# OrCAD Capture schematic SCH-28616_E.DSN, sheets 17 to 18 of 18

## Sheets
17 M-03 USB OTG / HOST: size C
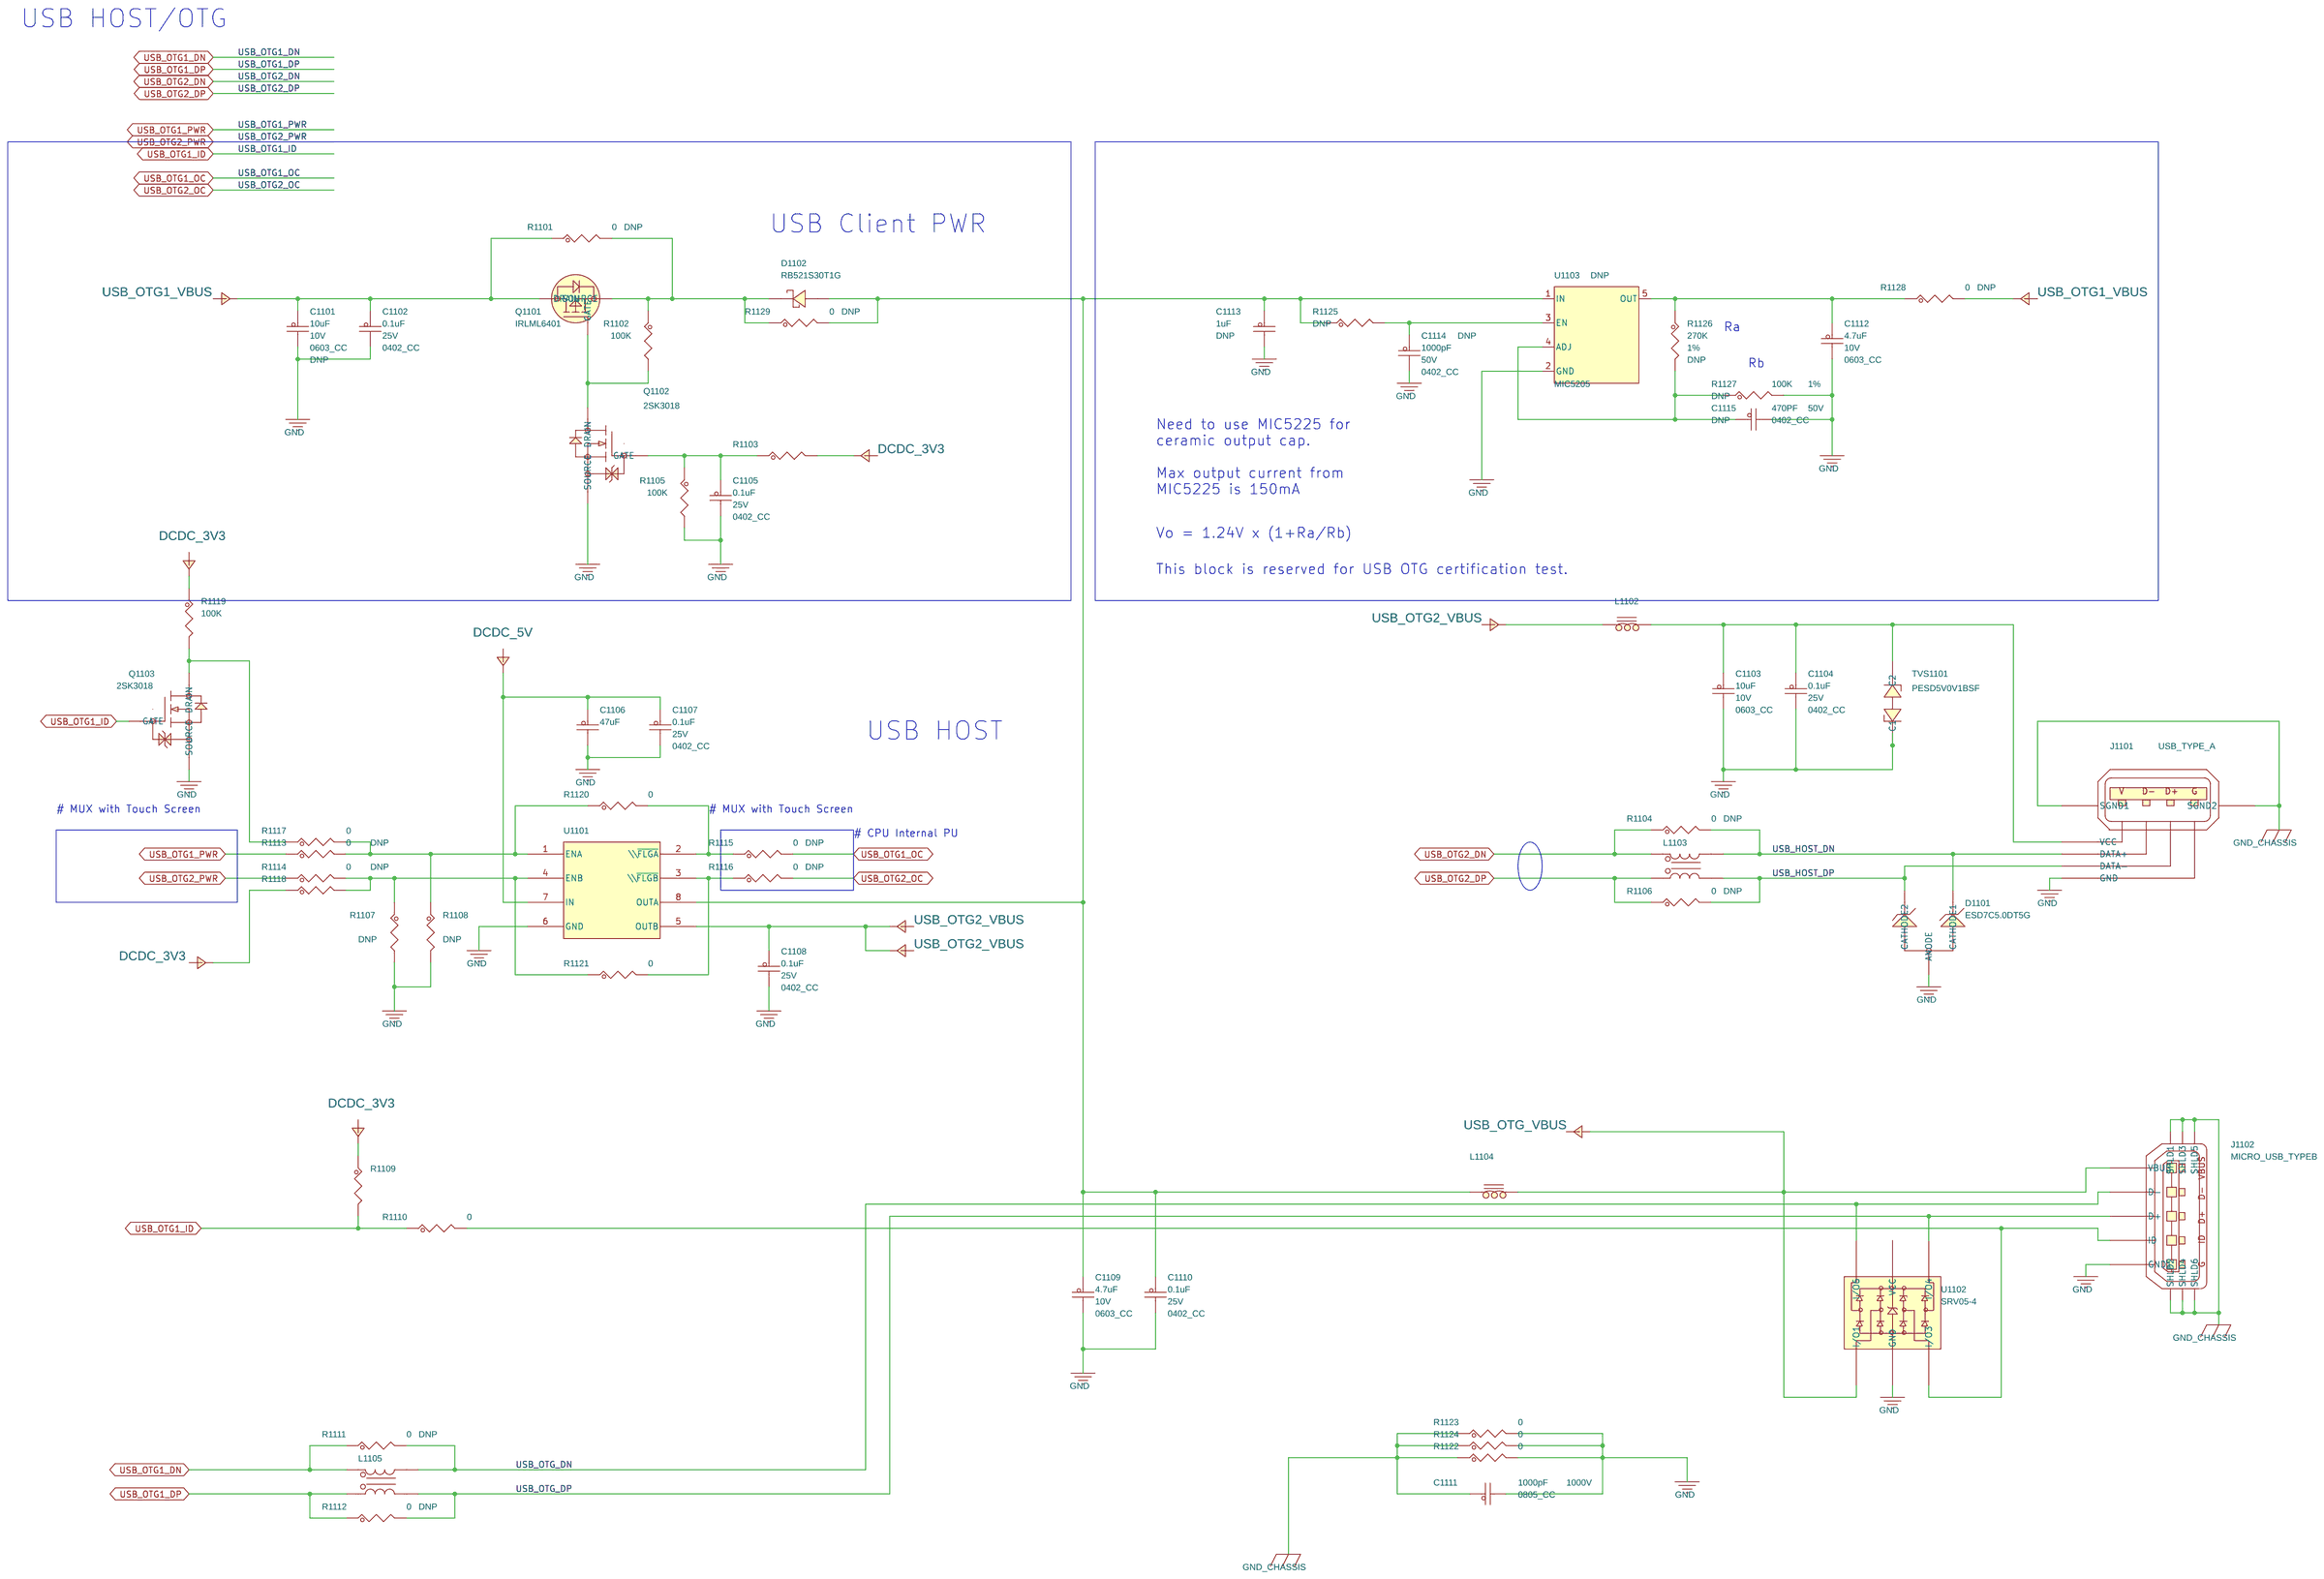
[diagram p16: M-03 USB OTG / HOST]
18 M-09 SD/BT/ARDUINO: size C
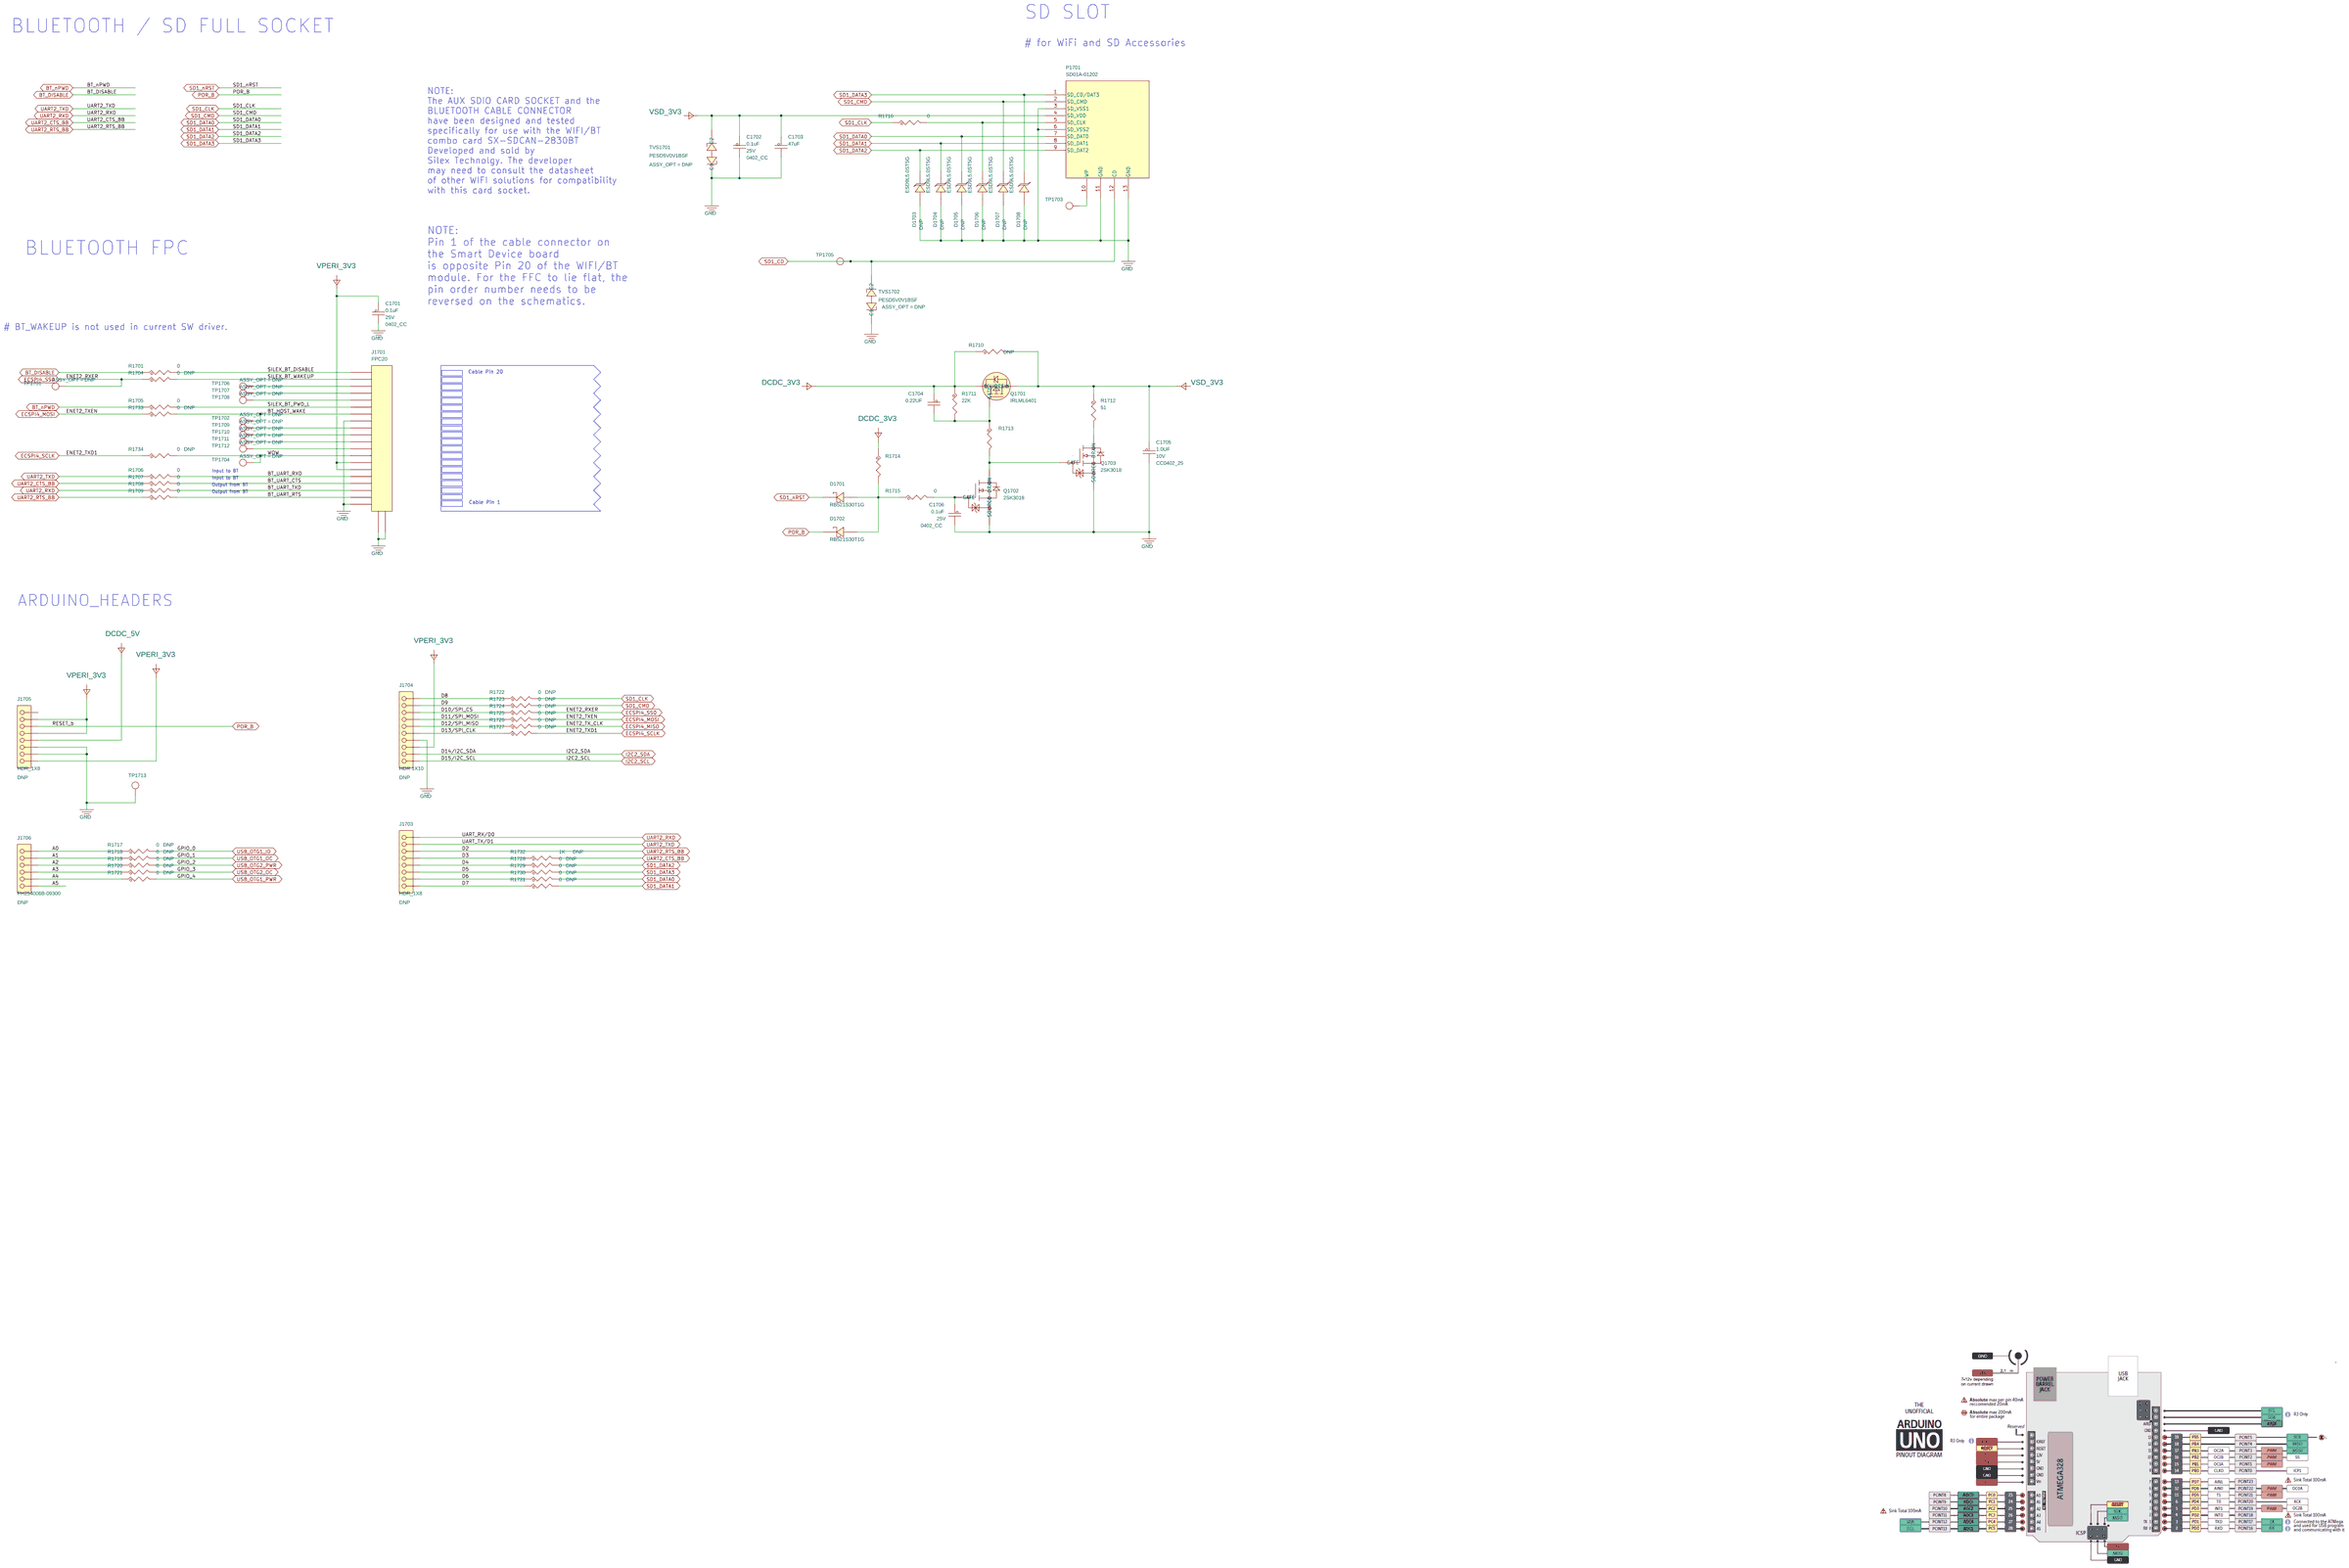
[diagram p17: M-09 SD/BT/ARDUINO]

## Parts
sheet M-03 USB OTG / HOST
C1101  10uF  [0603_CC]
C1102  0.1uF  [0402_CC]
C1103  10uF  [0603_CC]
C1104  0.1uF  [0402_CC]
C1105  0.1uF  [0402_CC]
C1106  47uF  [0805_CC]
C1107  0.1uF  [0402_CC]
C1108  0.1uF  [0402_CC]
C1109  4.7uF  [0603_CC]
C1110  0.1uF  [0402_CC]
C1111  1000pF  [0805_CC]
C1112  4.7uF  [0603_CC]
C1113  1uF  [0402_CC]
C1114  1000pF  [0402_CC]
C1115  470PF  [0402_CC]
D1101  ESD7C5.0DT5G  [sot-723]
D1102  RB521S30T1G  [sod_523]
J1101  USB_TYPE_A  [con4_usb_a_fe_ra_th]
J1102  MICRO_USB_TYPEB  [con_usb_type_b_sm]
L1102  120OHM  [0603_CC]
L1103  90OHM  [ind4_choke_0805]
L1104  120OHM  [0603_CC]
L1105  90OHM  [ind4_choke_0805]
Q1101  IRLML6401  [sot-23]
Q1102  2SK3018  [SOT323_3]
Q1103  2SK3018  [SOT323_3]
R1101  0  [0402_CC]
R1102  100K  [0402_CC]
R1103  10K  [0402_CC]
R1104  0  [0402_CC]
R1105  100K  [0402_CC]
R1106  0  [0402_CC]
R1107  10K  [0402_CC]
R1108  10K  [0402_CC]
R1109  10K  [0402_CC]
R1110  0  [0402_CC]
R1111  0  [0402_CC]
R1112  0  [0402_CC]
R1113  0  [0402_CC]
R1114  0  [0402_CC]
R1115  0  [0402_CC]
R1116  0  [0402_CC]
R1117  0  [0402_CC]
R1118  10K  [0402_CC]
R1119  100K  [0402_CC]
R1120  0  [0402_CC]
R1121  0  [0402_CC]
R1122  0  [0805_CC]
R1123  0  [0805_CC]
R1124  0  [0805_CC]
R1125  10K  [0402_CC]
R1126  270K  [RC0402_25]
R1127  100K  [RC0402_25]
R1128  0  [0402_CC]
R1129  0  [0402_CC]
TVS1101  PESD5V0V1BSF  [dsn0603-2]
U1101  MIC2026-1YM  [SO8]
U1102  SRV05-4  [SOT23_S6]
U1103  MIC5205  [sot23-20x60-5]
sheet M-09 SD/BT/ARDUINO
C1701  0.1uF  [0402_CC]
C1702  0.1uF  [0402_CC]
C1703  47uF  [0805_CC]
C1704  0.22UF  [CC0402_25]
C1705  1.0UF  [CC0402_25]
C1706  0.1uF  [0402_CC]
D1701  RB521S30T1G  [sod_523]
D1702  RB521S30T1G  [sod_523]
D1703  ESD9L5.0ST5G  [sod-923]
D1704  ESD9L5.0ST5G  [sod-923]
D1705  ESD9L5.0ST5G  [sod-923]
D1706  ESD9L5.0ST5G  [sod-923]
D1707  ESD9L5.0ST5G  [sod-923]
D1708  ESD9L5.0ST5G  [sod-923]
J1701  FPC20  [con_fpc_20_0p5_ra_f050_2sh]
J1703  HDR_1X8  [JUMP1X8-6040]
J1704  HDR 1X10  [hdr110]
J1705  HDR_1X8  [JUMP1X8-6040]
J1706  PH254006B-09300  [hdr106_b]
P1701  SD01A-01202  [con9_sdcard_28x29mm_smt]
Q1701  IRLML6401  [sot-23]
Q1702  2SK3018  [SOT323_3]
Q1703  2SK3018  [SOT323_3]
R1701  0  [0402_CC]
R1704  0  [0402_CC]
R1705  0  [0402_CC]
R1706  0  [0402_CC]
R1707  0  [0402_CC]
R1708  0  [0402_CC]
R1709  0  [0402_CC]
R1710  0  [0603_CC]
R1711  22K  [0402_CC]
R1712  51  [0402_CC]
R1713  10K  [0402_CC]
R1714  10K  [0402_CC]
R1715  0  [0402_CC]
R1716  0  [0402_CC]
R1717  0  [0402_CC]
R1718  0  [0402_CC]
R1719  0  [0402_CC]
R1720  0  [0402_CC]
R1721  0  [0402_CC]
R1722  0  [0402_CC]
R1723  0  [0402_CC]
R1724  0  [0402_CC]
R1725  0  [0402_CC]
R1726  0  [0402_CC]
R1727  0  [0402_CC]
R1728  0  [0402_CC]
R1729  0  [0402_CC]
R1730  0  [0402_CC]
R1731  0  [0402_CC]
R1732  1K  [0402_CC]
R1733  0  [0402_CC]
R1734  0  [0402_CC]
TP1701  TPAD_020  [tpad_020]
TP1702  TPAD_020  [tpad_020]
TP1703  TPAD_020  [tpad_020]
TP1704  TPAD_020  [tpad_020]
TP1705  TPAD_020  [tpad_020]
TP1706  TPAD_020  [tpad_020]
TP1707  TPAD_020  [tpad_020]
TP1708  TPAD_020  [tpad_020]
TP1709  TPAD_020  [tpad_020]
TP1710  TPAD_020  [tpad_020]
TP1711  TPAD_020  [tpad_020]
TP1712  TPAD_020  [tpad_020]
TP1713  TEST POINT WHITE  [TEST_LOOP]
TVS1701  PESD5V0V1BSF  [dsn0603-2]
TVS1702  PESD5V0V1BSF  [dsn0603-2]

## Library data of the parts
C1101 = CAP_NP: CAP CER 10UF 10V 20% X5R 0603; AGILE_PN: 150-78609; ASSY_OPT: DNP; CAD_APPROVED: Yes; FPLIST: CC0603_OV,CC0603,0603_CC; HEIGHT: 1.016MM; MFG_NAME01: TAIYO YUDEN; MFG_PN01: LMK107BJ106MALTD; Package Size: 0603; Package Type: Paper Tape; ROHS: Yes; Rated Voltage: 10V; Temp Range: -55C to +85C; Tolerance: 20%; VOLTAGE: 10V
C1102 C1104 C1105 C1107 C1108 C1110 C1701 C1702 C1706 = CAP_NP: CAP CER 0.1UF 25V 10% X5R 0402; AGILE_PN: 150-78633; CAD_APPROVED: Yes; FPLIST: CC0402_25,CC0402_HD,0402_CC; HEIGHT: 0.55MM; MFG_NAME01: YAGEO AMERICA; MFG_PN01: CC0402KRX5R8BB104; Package Size: 0402; ROHS: Yes; Rated Voltage: 25V; Temp Range: -55C to +85C; Tolerance: 10%; VOLTAGE: 25V
C1103 = CAP_NP: CAP CER 10UF 10V 20% X5R 0603; AGILE_PN: 150-78609; CAD_APPROVED: Yes; FPLIST: CC0603_OV,CC0603,0603_CC; HEIGHT: 1.016MM; MFG_NAME01: TAIYO YUDEN; MFG_PN01: LMK107BJ106MALTD; Package Size: 0603; Package Type: Paper Tape; ROHS: Yes; Rated Voltage: 10V; Temp Range: -55C to +85C; Tolerance: 20%; VOLTAGE: 10V
C1106 C1703 = CAP_NP: CAP CER 47uF 10V 20% X5R 0805; AGILE_PN: 150-78979; CAD_APPROVED: Yes; FPLIST: CC0805_OV,CC0805,0805_CC; HEIGHT: 1.45 MM; MFG_NAME01: TDK; MFG_PN01: C2012X5R1A476M125AC; ROHS: Yes; Rated Voltage: 10V; Temp Range: -55C to +85C; Tolerance: 20%; VOLTAGE: 10V
C1109 C1112 = CAP_NP: CAP CER 4.7UF 10V 10% X5R 0603; AGILE_PN: 150-77975; CAD_APPROVED: Yes; FPLIST: CC0603_OV,CC0603,0603_CC; HEIGHT: 0.9MM; MFG_NAME01: FENGHUA; MFG_PN01: 0603X475K100NT; Package Size: 0603; Package Type: tape & reel; ROHS: Yes; Rated Voltage: 10V; Temp Range: -55C to +85C; Tolerance: 10%; VOLTAGE: 10V
C1111 = CAP_NP: CAP CER 1000pF 1000V 10% X7R 0805; AGILE_PN: 150-78841; CAD_APPROVED: Yes; FPLIST: CC0805_OV,CC0805,0805_CC; HEIGHT: 1.4MM; MFG_NAME01: KEMET; MFG_PN01: C0805C102KDRACTU; Package Size: 0805; Package Type: Tape & reel; ROHS: Yes; Rated Voltage: 1000V; Temp Range: -55C to +125C; Tolerance: 10%; VOLTAGE: 1000V
C1113 = CAP_NP: CAP CER 1uF 16V 10% X5R 0402; AGILE_PN: 150-78973; ASSY_OPT: DNP; CAD_APPROVED: Yes; FPLIST: CC0402_25,CC0402_HD,0402_CC; HEIGHT: 0.55 MM; MFG_NAME01: YAGEO; MFG_PN01: CC0402KRX5R7BB105; ROHS: Yes; Rated Voltage: 16V; Temp Range: -55C to +85C; Tolerance: 10%; VOLTAGE: 16V
C1114 = CAP_NP: CAP CER 1000PF 50V X7R 5% 0402; AGILE_PN: 150-75774; ASSY_OPT: DNP; CAD_APPROVED: Yes; FPLIST: CC0402_25,CC0402_HD,0402_CC; HEIGHT: 0.6MM; MFG_NAME01: CAPAX TECHNOLOGIES INC.; MFG_PN01: 0402X102J500SNT; Package Size: 0402; Package Type: Tape&reel; ROHS: Yes; Rated Voltage: 50V; Temp Range: -55C to +125C; Tolerance: 5%; VOLTAGE: 50V
C1115 = CAP_NP: CAP CER 470PF 50V 10% X7R 0402; AGILE_PN: 150-75452; ASSY_OPT: DNP; CAD_APPROVED: Yes; FPLIST: CC0402_25,CC0402_HD,0402_CC; HEIGHT: 0.55MM; MFG_NAME01: WALSIN TECHNOLOGY CORP.; MFG_PN01: 0402B471K500CT; PRIORITY_PN: 021-00340; ROHS: Yes; ROOM: RGMII_PHY; Rated Voltage: 50V; SIGNAL_MODEL: DEFAULT_CAPACITOR_470pF_2_1; Temp Range: -55C to +125C; Tolerance: 10%; VOLTAGE: 50V
D1101 = DZ_DUAL_CK_C1C2A: DIODE TVS 1A 5.0V AEC-Q101 SOT-723; 3D_Mechanical_Footprint_File: http://fcl.am.freescale.net/ALLEGRO/step/sot-723.STEP; AGILE_PN: 480-78836; CAD_APPROVED: Yes; HEIGHT: 0.55MM; MFG_NAME01: ON SEMICONDUCTOR; ROHS: Yes; Rated Voltage: 5V
D1102 D1701 D1702 = DIODE_SCHTKY: DIODE SCH 200MA 30V AEC-Q101 SOD-523; 3D_Mechanical_Footprint_File: http://fcl.am.freescale.net/ALLEGRO/step/sod_523.STEP; AGILE_PN: 480-78501; CAD_APPROVED: Yes; HEIGHT: 0.7MM; MFG_NAME01: ON SEMICONDUCTOR; ROHS: Yes; Rated Voltage: 30V
J1101 = USB_A: CON 1X4 RA SHLD TH USB_TYPE_A_FEMALE -- 321H AU 118L; AGILE_PN: 210-80779; CAD_APPROVED: Yes; HEIGHT: 8.15MM; MFG_NAME01: SHENZHEN ATOM TECHNOLOGY CO.,LTD; MFG_PN01: USB304FA-A1005302; Package Type: TH; ROHS: Yes
J1102 = USB_MICRO_B_SKT: CON 1X5 MICROUSB_TYPE_B_FEMALE RA SHLD SMT 0.65MM SP 110H AU; AGILE_PN: 211-79712; CAD_APPROVED: Yes; HEIGHT: 2.795MM; MFG_NAME01: SHENZHEN ATOM TECHNOLOGY CO.,LTD; MFG_PN01: USB205FB-C1013203; ROHS: Yes
L1102 L1104 = BEAD_0: IND FER BEAD 120OHM@100MHZ 2A 25% 0603; AGILE_PN: 180-30008; CAD_APPROVED: Yes; FPLIST: IND_0603,0603_CC; HEIGHT: 0.95MM; MFG_NAME01: MURATA; MFG_PN01: BLM18PG121SH1; PART_TYPE: FERRITE; ROHS: Yes; Tolerance: 25%
L1103 L1105 = DLW43: IND CHK 90 OHM@100MHZ 330MA 25% 0805; 3D_Mechanical_Footprint_File: http://fcl.am.freescale.net/ALLEGRO/step/ind4_choke_0805_39h.STEP; AGILE_PN: 180-76336; CAD_APPROVED: Yes; HEIGHT: 1MM; MFG_NAME01: MURATA; MFG_PN01: DLW21HN900SQ2L; PART_TYPE: CHOKE; ROHS: Yes; Temp Range: -40°C to +85°C; Tolerance: 25%
Q1101 Q1701 = MOSFET_P: TRAN PMOS PWR 12V 4.3A SOT23; AGILE_PN: 480-77718; CAD_APPROVED: Yes; HEIGHT: 1.12MM; MFG_NAME01: INTERNATIONAL RECTIFIER; MFG_PN01: IRLML6401TRPBF; ROHS: Yes
Q1102 Q1103 Q1702 Q1703 = 2SK3018: TRANS MOSFET N-CH 30V .1A SOT-323; AGILE_PN: 480-75317; CAD_APPROVED: Yes; HEIGHT: 0.9MM; MFG_NAME01: ROHM; MFG_PN01: 2SK3018T106; ROHS: Yes
R1101 R1104 R1106 R1111-R1116 R1128 R1129 R1704 R1717-R1731 R1733 R1734 = RES: RES MF ZERO OHM 1/16W 5% 0402; AGILE_PN: 470-75394; ASSY_OPT: DNP; CAD_APPROVED: Yes; FPLIST: RC0402_25,RC0402_HD,RC0402_X2,0402_CC; HEIGHT: 0.45 MM; MFG_NAME01: YAGEO AMERICA; MFG_PN01: RC0402JR-070RL; ROHS: Yes; Tolerance: 5%
R1102 R1105 R1119 = RES: RES MF 100K 1/16W 5% 0402; AGILE_PN: 470-75597; CAD_APPROVED: Yes; FPLIST: RC0402_25,RC0402_HD,0402_CC; HEIGHT: 0.40 MM; MFG_NAME01: VENKEL COMPANY; MFG_PN01: CR0402-16W-104JT; ROHS: Yes; Temp Range: -55C to +155C; Temp_Range: -55C to +155C; Tolerance: 5%
R1103 R1109 R1118 = RES: RES MF 10K 1/16W 5% 0402; AGILE_PN: 470-75557; CAD_APPROVED: Yes; FPLIST: RC0402_25,RC0402_HD,0402_CC; HEIGHT: 0.4 MM; MFG_NAME01: VISHAY INTERTECHNOLOGY; MFG_PN01: CRCW040210K0JNED; ROHS: Yes; Tolerance: 5%
R1107 R1108 = RES: RES MF 10K 1/16W 5% 0402; AGILE_PN: 470-75557; ASSY_OPT: DNP; CAD_APPROVED: Yes; FPLIST: RC0402_25,RC0402_HD,0402_CC; HEIGHT: 0.4 MM; MFG_NAME01: VISHAY INTERTECHNOLOGY; MFG_PN01: CRCW040210K0JNED; ROHS: Yes; Tolerance: 5%
R1110 R1117 R1120 R1121 R1701 R1705-R1709 R1715 R1716 = RES: RES MF ZERO OHM 1/16W 5% 0402; AGILE_PN: 470-75394; CAD_APPROVED: Yes; FPLIST: RC0402_25,RC0402_HD,RC0402_X2,0402_CC; HEIGHT: 0.45 MM; MFG_NAME01: YAGEO AMERICA; MFG_PN01: RC0402JR-070RL; ROHS: Yes; Tolerance: 5%
R1122-R1124 = RES: RES MF ZERO OHM 1/8W -- 0805; AGILE_PN: 470-75442; CAD_APPROVED: Yes; FPLIST: RC0805_OV,RC0805,RC0805_OV_3P,0805_CC; HEIGHT: 0.7 MM; MFG_NAME01: YAGEO AMERICA; MFG_PN01: RC0805JR-070RL; ROHS: Yes; Temp Range: –55 °C to +155 °C; Tolerance: 5%
R1125 = RES: RES MF 10K 1/16W 5% 0402; AGILE_PN: 470-75557; ASSY_OPT: DNP; CAD_APPROVED: Yes; FPLIST: RC0402_25,RC0402_HD,0402_CC; HEIGHT: 0.4 MM; MFG_NAME01: VISHAY INTERTECHNOLOGY; MFG_PN01: CRCW040210K0JNED; ROHS: Yes; TOL: 5%; Tolerance: 5%
R1126 = RES: RES MF 270K 1/10W 1% AEC-Q200 0402; AGILE_PN: 470-31107; ASSY_OPT: DNP; CAD_APPROVED: Yes; FPLIST: RC0402_25,RC0402_HD,0402_CC; HEIGHT: 0.40 MM; MFG_NAME01: KOA SPEER; MFG_PN01: RK73H1ETTP2703F; ROHS: Yes; Temp Range: -55C to +155C; Temp_Range: -55C to +155C; Tolerance: 1%
R1127 = RES: RES MF 100K 1/16W 1% 0402; AGILE_PN: 470-76240; ASSY_OPT: DNP; CAD_APPROVED: Yes; FPLIST: RC0402_25,RC0402_HD,0402_CC; HEIGHT: 0.4MM; MFG_NAME01: VISHAY INTERTECHNOLOGY; MFG_PN01: CRCW0402100KFKEDC; ROHS: Yes; Tolerance: 1%
TVS1101 = DIODE_BIDIR: DIODE BIDIR ESD PROT 3.5pF 5V 1A SOD-962; 3D_Mechanical_Footprint_File: http://fcl.am.freescale.net/ALLEGRO/step/dsn0603-2.STEP; AGILE_PN: 480-79836; CAD_APPROVED: Yes; HEIGHT: 0.32MM; MFG_NAME01: NEXPERIA; MFG_PN01: PESD5V0V1BSF,315; Temp Range: -55°C to +150°C
U1101 = MIC2526_8P: IC LIN SW PWR ACTIVE HIGH DUAL 2.7V-5.5V 0.5A SOIC8; AGILE_PN: 312-75936; CAD_APPROVED: Yes; HEIGHT: 1.73mm; MFG_NAME01: MICREL; ROHS: Yes; VOLTAGE: 2.7-5.5V
U1102 = SRV05-4: DIODE TVS ARRAY 12A 5V 300W SOT23_S6; 3D_Mechanical_Footprint_File: http://fcl.am.freescale.net/ALLEGRO/step/SOT23_S6.STEP; AGILE_PN: 480-75205; CAD_APPROVED: Yes; HEIGHT: 1.45mm; MFG_NAME01: SEMTECH CORP; MFG_PN01: SRV05-4.TCT; ROHS: Yes; Rated Voltage: 5V
U1103 = MIC5205YM5_5P: IC LIN VREG LDO  1.5-15V 150MA 2.5-16V SOT23-5; 3D_Mechanical_Footprint_File: http://fcl.am.freescale.net/ALLEGRO/step/SOT23-20X60-5.STEP; AGILE_PN: 315-75304; ASSY_OPT: DNP; CAD_APPROVED: Yes; HEIGHT: 1.30MM; MFG_NAME01: MICREL; MFG_PN01: MIC5205YM5; ROHS: Yes; VOLTAGE: 2.5V to +16V
C1704 = CAP_NP: CAP CER 0.22UF 10V 10% X5R 0402; AGILE_PN: 150-77358; CAD_APPROVED: Yes; FPLIST: CC0402_25,CC0402_HD,0402_CC; HEIGHT: 0.55MM; MFG_NAME01: NIC COMPONENTS CORP; MFG_PN01: NMC0402X5R224K10TRPF; ROHS: Yes; Rated Voltage: 10V; Temp Range: -55C to +85C; Tolerance: 10%; VOLTAGE: 10V
C1705 = CAP_NP: CAP CER 1.0UF 10V 10% X5R 0402; AGILE_PN: 150-75772; CAD_APPROVED: Yes; FPLIST: CC0402_25,CC0402_HD,0402_CC; HEIGHT: 0.6MM; MFG_NAME01: YAGEO AMERICA; MFG_PN01: CC0402KRX5R6BB105; Package Size: 0402; ROHS: Yes; Rated Voltage: 10V; Temp Range: -55C to +85C; Tolerance: 10%; VOLTAGE: 10V
D1703-D1708 = DIODE_TVS: DIODE TVS ESD PROT ULT LOW CAP 5-5.4V SOD-923; 3D_Mechanical_Footprint_File: http://fcl.am.freescale.net/ALLEGRO/step/sod-923.STEP; AGILE_PN: 480-77934; ASSY_OPT: DNP; CAD_APPROVED: Yes; HEIGHT: 0.40MM; MFG_NAME01: ON SEMICONDUCTOR; ROHS: Yes
J1701 = CON20_2SH: CON 1X20 FPC/FFC RA SKT SMT 0.5MM SP 87H SN; AGILE_PN: 211-79307; CAD_APPROVED: Yes; FPLIST: con_fpc_20_0p5_ra_f050,con_fpc_20_0p5_ra_f050_2sh; HEIGHT: 2.2 MM; MFG_NAME01: SHENZHEN ATOM TECHNOLOGY CO.,LTD; MFG_PN01: F05020-S030105A08200; ROHS: Yes
J1703 J1705 = CONN_HDR_8X1: HDR 1X8 TH 100MIL SP 347H AU 118L; 3D_Mechanical_Footprint_File: http://fcl.am.freescale.net/ALLEGRO/step/jump1x8-6040_200l.STEP; AGILE_PN: 210-80829; ASSY_OPT: DNP; CAD_APPROVED: Yes; HEIGHT: 8.8MM; MFG_NAME01: SHENZHEN ATOM TECHNOLOGY CO.,LTD; MFG_PN01: PH254008B-09300; ROHS: Yes; Temp Range: -55°C to +105°C
J1704 = CONN_HDR_10X1: HDR 1X10 TH 100MIL SP 346H AU 118L; 3D_Mechanical_Footprint_File: http://fcl.am.freescale.net/ALLEGRO/step/hdr110.STEP; AGILE_PN: 210-80776; ASSY_OPT: DNP; CAD_APPROVED: Yes; HEIGHT: 8.8MM; MFG_NAME01: SHENZHEN ATOM TECHNOLOGY CO.,LTD; MFG_PN01: PH254010B-09300; ROHS: Yes; Temp Range: -55°C to +105°C
J1706 = CONN_HDR_6X1: HDR 1X6 TH 100MIL SP 347H AU 118L; AGILE_PN: 210-80828; ASSY_OPT: DNP; CAD_APPROVED: Yes; HEIGHT: 8.8MM; MFG_NAME01: SHENZHEN ATOM TECHNOLOGY CO.,LTD; ROHS: Yes
P1701 = SD_SOCKET_SMT: CON 9 SD CARD SKT SMT 2.5MM -- 114H AU; AGILE_PN: TMP-WF-24049; CAD_APPROVED: Yes; HEIGHT: 2.9MM; MFG_NAME01: SHENZHEN ATOM TECHNOLOGY CO.,LTD; PRE_APN: 211-79703; Package Type: SMT; ROHS: Yes
R1710 = RES: RES MF ZERO OHM 1/10W -- AEC-Q200 0603; AGILE_PN: 470-75407; ASSY_OPT: DNP; CAD_APPROVED: Yes; FPLIST: RC0603_OV,RC0603,R603-X2,0603_CC; HEIGHT: 0.6MM; MFG_NAME01: PANASONIC; MFG_PN01: ERJ-3GEY0R00V; ROHS: Yes; Temp Range: –55 °C to +155 °C; Tolerance: 1%
R1711 = RES: RES MF 22K 1/16W 5% 0402; AGILE_PN: 470-75609; CAD_APPROVED: Yes; FPLIST: RC0402_25,RC0402_HD,0402_CC; HEIGHT: 0.41mm; MFG_NAME01: SMEC; MFG_PN01: RC73L2Z223JTF; ROHS: Yes; Tolerance: 5%
R1712 = RES: RES MF 51 OHM 1/16W 5% 0402; AGILE_PN: 470-76089; CAD_APPROVED: Yes; FPLIST: RC0402_25,RC0402_HD,0402_CC; HEIGHT: 0.40 MM; MFG_NAME01: YAGEO AMERICA; MFG_PN01: RC0402JR-0751RL; ROHS: Yes; Tolerance: 5%
R1713 R1714 = RES: RES MF 10K 1/16W 5% 0402; AGILE_PN: 470-75557; CAD_APPROVED: Yes; FPLIST: RC0402_25,RC0402_HD,0402_CC; HEIGHT: 0.4 MM; MFG_NAME01: VISHAY INTERTECHNOLOGY; MFG_PN01: CRCW040210K0JNED; ROHS: Yes; TOL: 5%; Tolerance: 5%
R1732 = RES: RES MF 1.0K 1/16W 5% 0402; AGILE_PN: 470-75555; ASSY_OPT: DNP; CAD_APPROVED: Yes; FPLIST: RC0402_25,RC0402_HD,RC0402_X2,0402_CC; HEIGHT: 0.41mm; MFG_NAME01: VISHAY INTERTECHNOLOGY; MFG_PN01: CRCW04021K00JNED; ROHS: Yes; Tolerance: 5%
TP1701 TP1702 TP1704 TP1706-TP1712 = TESTLOOP: TEST POINT PAD 0.5MM DIA SMT, NO PART TO ORDER; AGILE_PN: 211-77484; ASSY_OPT: DNP; CAD_APPROVED: Yes; HEIGHT: 0.1MM; ROHS: Yes
TP1703 TP1705 = TESTLOOP: TEST POINT PAD 0.5MM DIA SMT, NO PART TO ORDER; AGILE_PN: 211-77484; CAD_APPROVED: Yes; HEIGHT: 0.1MM; ROHS: Yes
TP1713 = TESTLOOP: TEST POINT WHITE 40 MIL DRILL 180 MIL TH 109L; AGILE_PN: 210-75685; CAD_APPROVED: Yes; HEIGHT: 4.8 MM; MFG_NAME01: KEYSTONE ELECTRONICS; MFG_PN01: 5002; ROHS: Yes; Temp Range: -50°C to +146°C
TVS1701 TVS1702 = DIODE_BIDIR: DIODE BIDIR ESD PROT 3.5pF 5V 1A SOD-962; 3D_Mechanical_Footprint_File: http://fcl.am.freescale.net/ALLEGRO/step/dsn0603-2.STEP; AGILE_PN: 480-79836; ASSY_OPT: DNP; CAD_APPROVED: Yes; HEIGHT: 0.32MM; MFG_NAME01: NEXPERIA; MFG_PN01: PESD5V0V1BSF,315; Temp Range: -55°C to +150°C

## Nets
GND: C1101.2 C1102.2 C1103.2 C1104.2 C1105.2 C1106.2 C1107.2 C1108.2 C1109.2 C1110.2 C1111.2 C1112.2 C1113.2 C1114.2 C1115.2 C1701.2 C1702.2 C1703.2 C1705.2 C1706.2 D1101.3(ANODE) D1703.A D1704.A D1705.A D1706.A D1707.A D1708.A J1101.A4(GND) J1102.5(GND1) J1701.8 J1701.20 J1701.S1 J1701.S2 J1704.7 J1705.6 J1705.7 P1701.3(SD_VSS1) P1701.6(SD_VSS2) P1701.11(GND) P1701.13(GND) Q1102.1(SOURCE) Q1103.1(SOURCE) Q1702.1(SOURCE) Q1703.1(SOURCE) R1105.2 R1107.2 R1108.2 R1122.2 R1123.2 R1124.2 R1127.2 TP1713.1(Pin1) TVS1101.1(C1) TVS1701.1(C1) TVS1702.1(C1) U1101.6(GND) U1102.2(GND) U1103.2(GND) ; also on sheet 3 4 5 6 7 8 12 13 14 15 16
GND_CHASSIS: C1111.1 J1101.S1(SGND1) J1101.S2(SGND2) J1102.S1(SHLD1) J1102.S2(SHLD2) J1102.S3(SHLD3) J1102.S4(SHLD4) J1102.S5(SHLD5) J1102.S6(SHLD6) R1122.1 R1123.1 R1124.1 ; also on sheet 13 14
A0: J1706.1 R1717.1
A1: J1706.2 R1718.1
A2: J1706.3 R1719.1
A3: J1706.4 R1720.1
A4: J1706.5 R1721.1
A5: J1706.6
BT_DISABLE: R1701.1 ; also on sheet 3
BT_HOST_WAKE: J1701.7 R1733.2 TP1702.1(Pin1)
BT_nPWD: R1705.1 ; also on sheet 3
BT_UART_CTS: J1701.17 R1707.2
BT_UART_RTS: J1701.19 R1709.2
BT_UART_RXD: J1701.16 R1706.2
BT_UART_TXD: J1701.18 R1708.2
D3: J1703.4 R1732.1
D4: J1703.5 R1728.1
D5: J1703.6 R1729.1
D6: J1703.7 R1730.1
D7: J1703.8 R1731.1
D8: J1704.1 R1722.1
D9: J1704.2 R1723.1
D10/SPI_CS: J1704.3 R1724.1
D11/SPI_MOSI: J1704.4 R1725.1
D12/SPI_MISO: J1704.5 R1726.1
D13/SPI_CLK: J1704.6 R1727.1
DCDC_3V3: C1704.1 Q1701.2(SOURCE) R1103.2 R1109.1 R1118.1 R1119.1 R1710.1 R1711.1 R1714.1 ; also on sheet 3 4 8 12 16
DCDC_5V: C1106.1 C1107.1 J1705.5 U1101.7(IN) ; also on sheet 7 12 15
ECSPI4_MISO: R1726.2 ; also on sheet 3 8 14
ECSPI4_MOSI: R1725.2 R1733.1 ; also on sheet 3 8 14
ECSPI4_SCLK: R1727.2 R1734.1 ; also on sheet 3 8 14
ECSPI4_SS0: R1704.1 R1724.2 TP1701.1(Pin1) ; also on sheet 3 8 14
I2C2_SCL: J1704.10 ; also on sheet 3 4 5 8 12
I2C2_SDA: J1704.9 ; also on sheet 3 4 5 8 12
POR_B: D1702.C J1705.3 ; also on sheet 3 16
SD1_CD: P1701.12(CD) TP1705.1(Pin1) TVS1702.2(C2) ; also on sheet 3
SD1_CLK: R1716.1 R1722.2 ; also on sheet 3
SD1_CMD: D1707.C P1701.2(SD_CMD) R1723.2 ; also on sheet 3
SD1_DATA0: D1705.C P1701.7(SD_DAT0) R1730.2 ; also on sheet 3
SD1_DATA1: D1704.C P1701.8(SD_DAT1) R1731.2 ; also on sheet 3
SD1_DATA2: D1703.C P1701.9(SD_DAT2) R1728.2 ; also on sheet 3
SD1_DATA3: D1708.C P1701.1(SD_CD/DAT3) R1729.2 ; also on sheet 3
SD1_nRST: D1701.C ; also on sheet 3
SILEX_BT_DISABLE: J1701.1 R1701.2
SILEX_BT_PWD_L: J1701.6 R1705.2
SILEX_BT_WAKEUP: J1701.2 R1704.2
UART2_CTS_BB: R1707.1 R1732.2 ; also on sheet 3
UART2_RTS_BB: J1703.3 R1709.1 ; also on sheet 3
UART2_RXD: J1703.1 R1708.1 ; also on sheet 3
UART2_TXD: J1703.2 R1706.1 ; also on sheet 3
USB_HOST_DN: D1101.1(CATHODE1) J1101.A2(DATA+) L1103.2 R1104.2
USB_HOST_DP: D1101.2(CATHODE2) J1101.A3(DATA-) L1103.3 R1106.2
USB_HOST_VBUS: C1108.1 L1102.1 U1101.5(OUTB) ; also on sheet 3
USB_OTG1_DN: L1105.1 R1111.1 ; also on sheet 3
USB_OTG1_DP: L1105.4 R1112.1 ; also on sheet 3
USB_OTG1_ID: Q1103.2(GATE) R1109.2 R1110.1 R1717.2 ; also on sheet 3
USB_OTG1_OC: R1115.2 R1718.2 ; also on sheet 3 8
USB_OTG1_PWR: R1113.1 R1721.2 ; also on sheet 3 8 15
USB_OTG1_VBUS: C1101.1 C1102.1 Q1101.3(DRAIN) R1101.1 R1128.2 ; also on sheet 3
USB_OTG2_DN: L1103.1 R1104.1 ; also on sheet 3
USB_OTG2_DP: L1103.4 R1106.1 ; also on sheet 3
USB_OTG2_OC: R1116.2 R1720.2 ; also on sheet 3 8
USB_OTG2_PWR: R1114.1 R1719.2 ; also on sheet 3 8
USB_OTG_DN: J1102.2(D-) L1105.2 R1111.2 U1102.6(I/O6)
USB_OTG_DP: J1102.3(D+) L1105.3 R1112.2 U1102.4(I/O4)
USB_OTG_VBUS: J1102.1(VBUS) L1104.2 U1102.1(I/O1)
VENET_3V3: C1701.1 J1701.14 J1701.15 J1704.8 J1705.2 J1705.4 J1705.8 ; also on sheet 3 4 5 6 7 13 14 15
VSD_3V3: C1702.1 C1703.1 C1705.1 P1701.4(SD_VDD) Q1701.3(DRAIN) R1710.2 R1712.1 TVS1701.2(C2)
WOW: J1701.13 R1734.2 TP1704.1(Pin1)
N97050984: Q1101.1(GATE) Q1102.3(DRAIN) R1102.2
N97051024: C1105.1 Q1102.2(GATE) R1103.1 R1105.1
N97051721: J1102.4(ID) R1110.2 U1102.3(I/O3)
N97051725: C1109.1 C1110.1 C1113.1 D1102.A L1104.1 R1125.1 R1129.2 U1101.8(OUTA) U1103.1(IN)
N97051938: D1102.C Q1101.2(SOURCE) R1101.2 R1102.1 R1129.1
N97081112: Q1703.3(DRAIN) R1712.2
N97081468: D1701.A D1702.A R1714.2 R1715.1
N97081502: C1704.2 Q1701.1(GATE) R1711.2 R1713.1
N97085045: R1115.1 R1120.2 U1101.2(\\~{FLGA})
N97085099: R1107.1 R1114.2 R1118.2 R1121.1 U1101.4(ENB)
N97085121: R1108.1 R1113.2 R1117.2 R1120.1 U1101.1(ENA)
N97085690: C1103.1 C1104.1 J1101.A1(VCC) L1102.2 TVS1101.2(C2)
N97185823: P1701.10(WP) TP1703.1(Pin1)
N97565569: C1706.1 Q1702.2(GATE) R1715.2
N97565776: Q1702.3(DRAIN) Q1703.2(GATE) R1713.2
N97797261: R1116.1 R1121.2 U1101.3(\\~{FLGB})
N98583961: Q1103.3(DRAIN) R1117.1 R1119.2
N98831920: D1706.C P1701.5(SD_CLK) R1716.2
N99086135: C1114.1 R1125.2 U1103.3(EN)
N99086182: C1115.1 R1126.2 R1127.1 U1103.4(ADJ)
N99086321: C1112.1 R1126.1 R1128.1 U1103.5(OUT)
N99305307: J1701.3 TP1706.1(Pin1)
N99305310: J1701.4 TP1707.1(Pin1)
N99305313: J1701.5 TP1708.1(Pin1)
N99305316: J1701.9 TP1709.1(Pin1)
N99305319: J1701.10 TP1710.1(Pin1)
N99305322: J1701.11 TP1711.1(Pin1)
N99305325: J1701.12 TP1712.1(Pin1)

Not connected (* = marked no-connect by the designer): J1705 1; U1102 5(VCC)

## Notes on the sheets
sheet 17
- USB HOST/OTG
- USB Client PWR
- Ra
- Rb
- Need to use MIC5225 for
  ceramic output cap.
  Max output current from
  MIC5225 is 150mA
- Vo = 1.24V x (1+Ra/Rb)
- This block is reserved for USB OTG certification test.
- USB HOST
- # MUX with Touch Screen
- # MUX with Touch Screen
- # CPU Internal PU
sheet 18
- SD SLOT
- BLUETOOTH / SD FULL SOCKET
- # for WiFi and SD Accessories
- NOTE:
  The AUX SDIO CARD SOCKET and the
  BLUETOOTH CABLE CONNECTOR
  have been designed and tested
  specifically for use with the WIFI/BT
  combo card SX-SDCAN-2830BT
  Developed and sold by
  Silex Technolgy. The developer
  may need to consult the datasheet
  of other WIFI solutions for compatibility
  with this card socket.
- NOTE:
  Pin 1 of the cable connector on
  the Smart Device board
  is opposite Pin 20 of the WIFI/BT
  module. For the FFC to lie flat, the
  pin order number needs to be
  reversed on the schematics.
- BLUETOOTH FPC
- # BT_WAKEUP is not used in current SW driver.
- Cable Pin 20
- Input to BT
- Input to BT
- Output from BT
- Output from BT
- Cable Pin 1
- ARDUINO_HEADERS
